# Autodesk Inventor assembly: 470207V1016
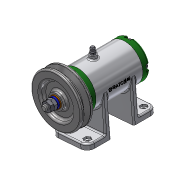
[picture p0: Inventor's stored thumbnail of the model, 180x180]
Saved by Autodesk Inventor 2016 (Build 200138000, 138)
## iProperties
Created: 2017-02
Part Number: 470207V1016
Material: 일반
Document SubType Name: Assembly
Designer: H
Author: H
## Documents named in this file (16)
- C:\Users\CAMTIC\Desktop\470207V1016\470207V1016.iam
- C:\Users\CAMTIC\Desktop\470207V1016\470207V1016.ipt
- C:\Users\CAMTIC\Desktop\470207V1016\V벨트풀리.ipt
- C:\Users\CAMTIC\Desktop\470207V1016\너트 M 8.ipt
- C:\Users\CAMTIC\Desktop\470207V1016\니플 M 6 x 0.75.ipt
- C:\Users\CAMTIC\Desktop\470207V1016\뒤커버.ipt
- C:\Users\CAMTIC\Desktop\470207V1016\베어링 15 x 32 x 9.ipt
- C:\Users\CAMTIC\Desktop\470207V1016\볼트 M 6 x 8.ipt
- C:\Users\CAMTIC\Desktop\470207V1016\볼트 M4 x 12.ipt
- C:\Users\CAMTIC\Desktop\470207V1016\스프링와셔 8.ipt
- C:\Users\CAMTIC\Desktop\470207V1016\앞커버.ipt
- C:\Users\CAMTIC\Desktop\470207V1016\오일 실 15 25 7.ipt
- C:\Users\CAMTIC\Desktop\470207V1016\와셔 6x11.5.ipt
- C:\Users\CAMTIC\Desktop\470207V1016\와셔 8x17.ipt
- C:\Users\CAMTIC\Desktop\470207V1016\축.ipt
- C:\Users\CAMTIC\Desktop\470207V1016\키 3 x 3 x 12.ipt
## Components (12 placed, 4 different names)
1. 470207V1016:1
2. V벨트풀리:1
3. KS B 2023 6002 - 15 x 32 x 9:1
4. KS B 2023 6002 - 15 x 32 x 9:2
5. ISO 4762 M4 x 12:1
6. ISO 4762 M4 x 12:3
7. ISO 4762 M4 x 12:4
8. ISO 4762 M4 x 12:5
9. ISO 4762 M4 x 12:2
10. ISO 4762 M4 x 12:6
11. ISO 4762 M4 x 12:7
12. ISO 4762 M4 x 12:8
